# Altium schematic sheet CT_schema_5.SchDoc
size 366 x 245 mm
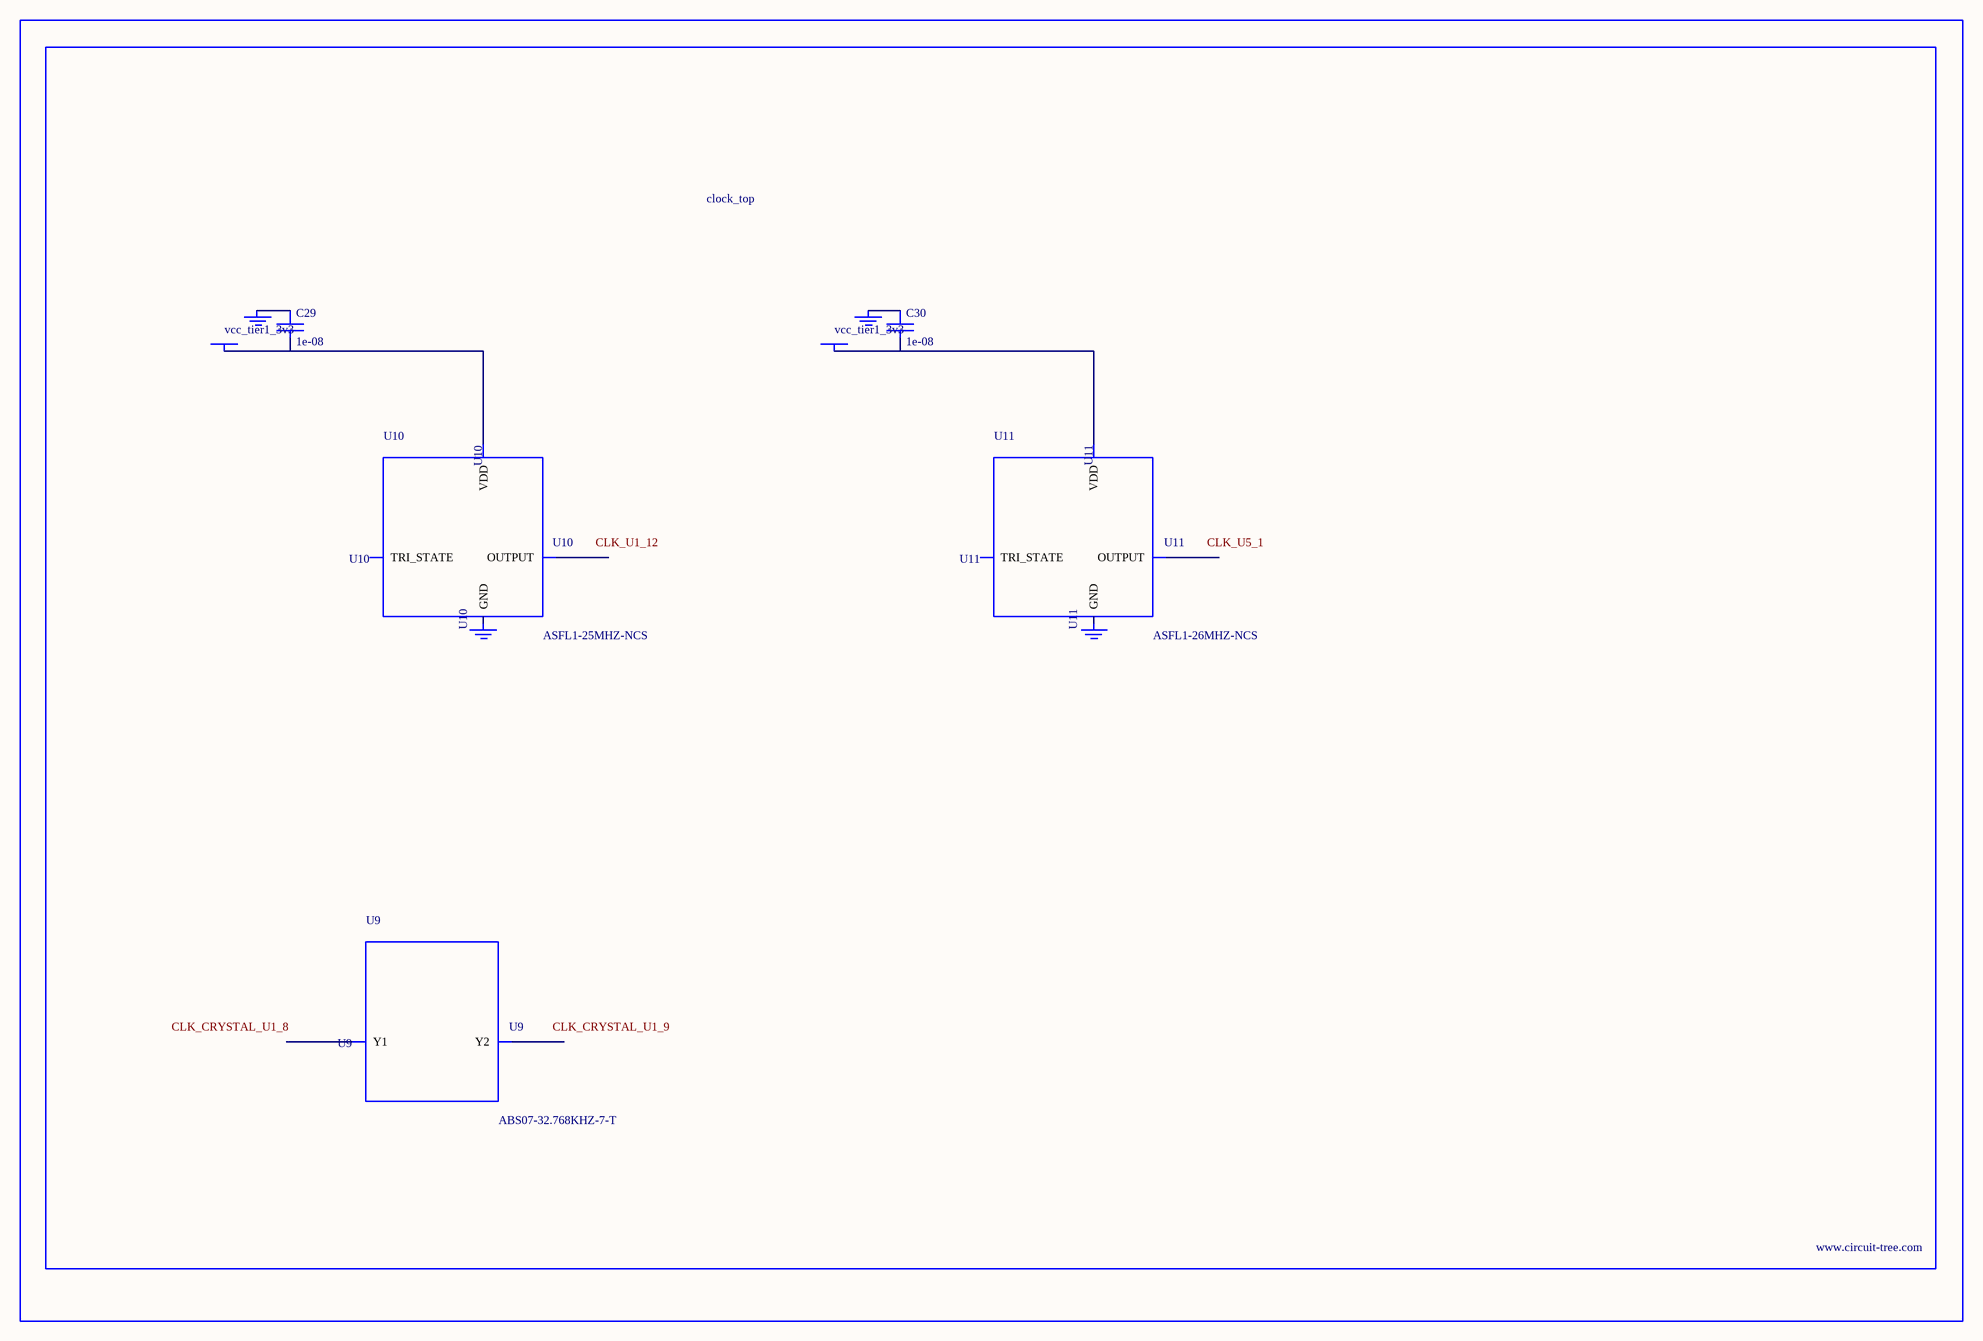
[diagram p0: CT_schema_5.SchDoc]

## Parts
BORDER4  (no value)
C29  1e-08  [C0402]
C30  1e-08  [C0402]
GND_INSTANCE_4_0  (no value)
GND_INSTANCE_4_1  (no value)
GND_INSTANCE_4_2  (no value)
GND_INSTANCE_4_3  (no value)
POWER_INSTANCE_4_0  vcc_tier1_3v3
POWER_INSTANCE_4_1  vcc_tier1_3v3
U9  ABS07-32.768KHZ-7-T  [ABS07-32.768KHZ-7-T]
U10  ASFL1-25MHZ-NCS  [ASFL1]
U11  ASFL1-26MHZ-NCS  [ASFL1]

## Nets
NetC29_1: C29.1 GND_INSTANCE_4_0.0(GND)
NetC29_2: C29.2 POWER_INSTANCE_4_0.0(PWR) U10.4(VDD)
NetC30_1: C30.1 GND_INSTANCE_4_2.0(GND)
NetC30_2: C30.2 POWER_INSTANCE_4_1.0(PWR) U11.4(VDD)

Not connected (* = marked no-connect by the designer): GND_INSTANCE_4_1 0(GND); GND_INSTANCE_4_3 0(GND); U9 1(Y1) 2(Y2); U10 1(TRI_STATE) 2(GND) 3(OUTPUT); U11 1(TRI_STATE) 2(GND) 3(OUTPUT)

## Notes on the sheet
- Labels drawn without touching a wire or pin: CLK_CRYSTAL_U1_8, CLK_CRYSTAL_U1_9, CLK_U1_12, CLK_U5_1

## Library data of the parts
BORDER4 = BORDER_PAGE4
C29 C30 = C0402C103K3RAC
GND_INSTANCE_4_0-GND_INSTANCE_4_3 = GND
POWER_INSTANCE_4_0 POWER_INSTANCE_4_1 = PWR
